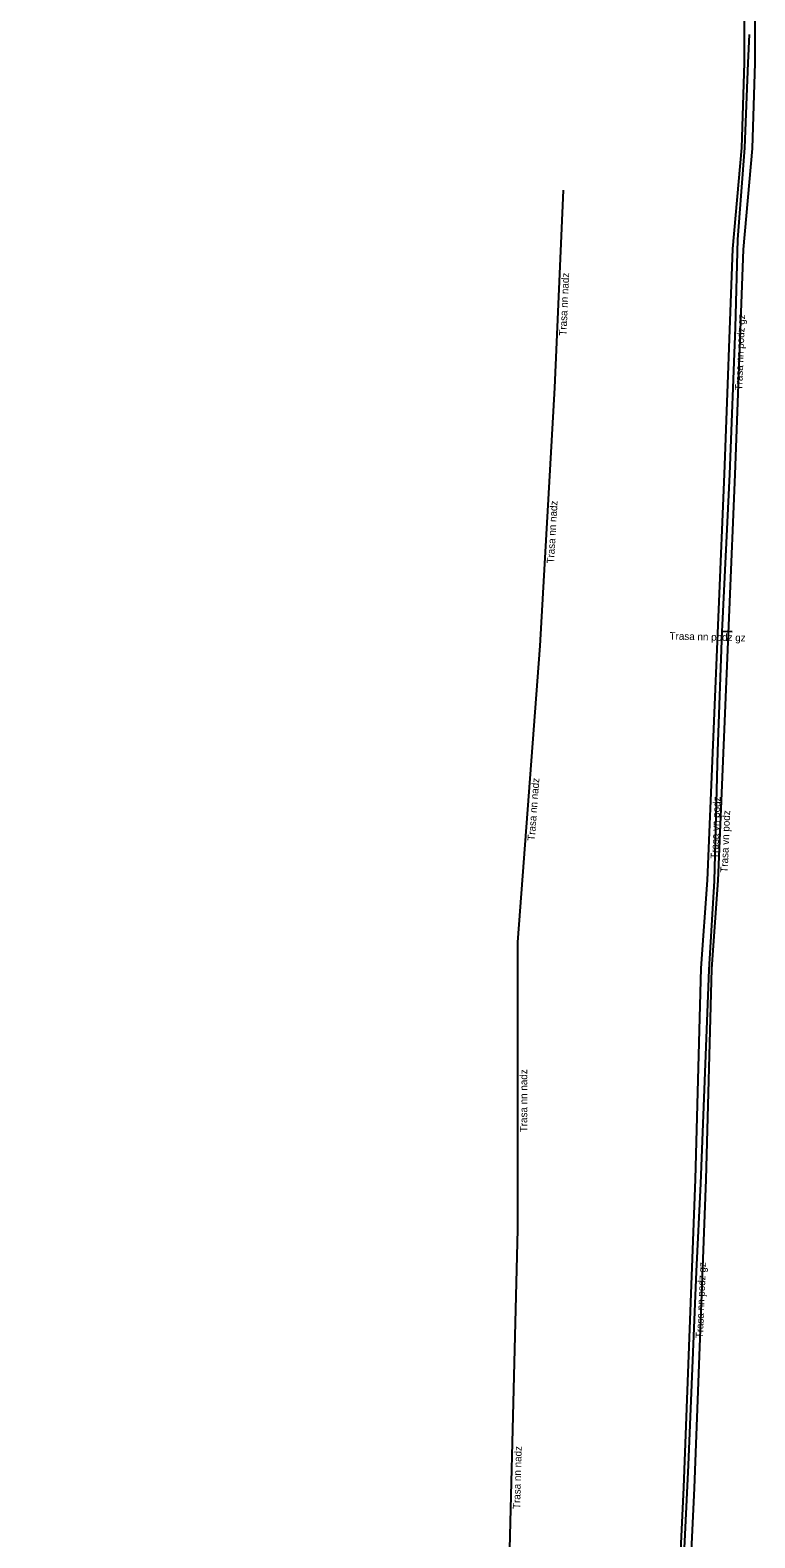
# Model space of a CAD drawing. Extents: x -746878 to -746498, y -1019831 to -1019251.
# Drawn here: x -746755.6 to -746706.4, y -1019452.3 to -1019350 of the extents above; entities that cross this region are included whole.
import ezdxf

# ---------------------------------------------------------------- set-up
doc = ezdxf.new("R2010")
doc.units = 0
for name, color, linetype in [('Popiskový text - Ostatní atributy Trasy', 7, 'Continuous'), ('Spojnice NN', 7, 'Continuous'), ('Spojnice VN', 7, 'Continuous')]:
    doc.layers.add(name, color=color, linetype=linetype)

msp = doc.modelspace()

# ---------------------------------------------------------------- linework, layer by layer
at = {"layer": 'Spojnice NN'}
for points in [[(-746706.79, -1019350.32), (-746706.88, -1019352.25), (-746707.1, -1019358.03), (-746707.57, -1019364.23), (-746707.74, -1019370.2), (-746708.11, -1019380.16), (-746708.61, -1019390.39), (-746708.63, -1019390.81)], [(-746719.4, -1019360.9), (-746720, -1019374.3)], [(-746720, -1019374.3), (-746721, -1019391.8)], [(-746708.63, -1019390.81), (-746708.92, -1019398.94), (-746709.15, -1019407.74), (-746709.52, -1019413.78), (-746710.08, -1019428.28), (-746710.38, -1019434.25), (-746710.93, -1019447.39), (-746711.54, -1019460.07), (-746711.88, -1019466.06), (-746712.08, -1019472.33), (-746712.29, -1019478.82), (-746712.29, -1019478.92)], [(-746708.63, -1019390.81), (-746707.93, -1019390.83)], [(-746721, -1019391.8), (-746722.5, -1019411.9)], [(-746722.5, -1019411.9), (-746722.5, -1019431.4)], [(-746722.5, -1019431.4), (-746723.3, -1019463)]]:
    msp.add_lwpolyline(points, dxfattribs=at)
at = {"layer": 'Spojnice VN'}
for points in [[(-746755.6, -1019521.1), (-746752.06, -1019520.1), (-746740.46, -1019522.16), (-746728.59, -1019524.73), (-746725.34, -1019525.34), (-746724.12, -1019524.79), (-746723.32, -1019523.18), (-746722.87, -1019516.33), (-746722.26, -1019515.46), (-746714.66, -1019515.24), (-746713.68, -1019512.29), (-746712.64, -1019478.81), (-746711.22, -1019448.9), (-746710.43, -1019427.98), (-746710.03, -1019413.67), (-746709.61, -1019407.69), (-746708.46, -1019380.15), (-746707.88, -1019364.86), (-746707.28, -1019358.02), (-746707.09, -1019352.25), (-746707.09, -1019338.31)], [(-746706.39, -1019338.35), (-746706.39, -1019352.26), (-746706.58, -1019358.06), (-746707.18, -1019364.91), (-746707.76, -1019380.18), (-746708.91, -1019407.73), (-746709.33, -1019413.71), (-746709.73, -1019428.01), (-746710.52, -1019448.93), (-746711.94, -1019478.83), (-746712.47, -1019495.5), (-746712.99, -1019512.41), (-746714.15, -1019515.92), (-746721.89, -1019516.15), (-746722.18, -1019516.57), (-746722.63, -1019523.36), (-746723.6, -1019525.33), (-746725.25, -1019526.07), (-746740.59, -1019522.85), (-746752.02, -1019520.82), (-746755.11, -1019521.69)]]:
    msp.add_lwpolyline(points, dxfattribs=at)

# ---------------------------------------------------------------- texts
at = {"layer": 'Popiskový text - Ostatní atributy Trasy'}
for s, rotation, p in [('Trasa nn nadz', 87.4362, (-746719.19, -1019370.77)), ('Trasa nn podz gz', 87.8279, (-746707.25, -1019374.48)), ('Trasa nn nadz', 86.7295, (-746720.03, -1019386.23)), ('Trasa nn podz gz', 358.5312, (-746712.19, -1019391.37)), ('Trasa nn nadz', 85.7321, (-746721.34, -1019405.04)), ('Trasa vn podz', 87.6214, (-746708.9, -1019406.26)), ('Trasa vn podz', 87.6181, (-746708.24, -1019407.2)), ('Trasa nn nadz', 90, (-746721.85, -1019424.8)), ('Trasa nn podz gz', 87.6329, (-746709.92, -1019438.78)), ('Trasa nn nadz', 88.5498, (-746722.33, -1019450.36))]:
    msp.add_text(s, height=0.5, rotation=rotation, dxfattribs=at).set_placement(p)

doc.saveas('drawing.dxf')
